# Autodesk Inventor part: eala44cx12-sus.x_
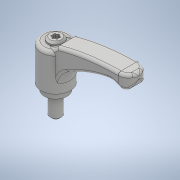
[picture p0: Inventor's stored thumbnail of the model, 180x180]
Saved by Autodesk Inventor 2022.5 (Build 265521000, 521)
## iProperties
Created: 2018-05
Part Number: eala44cx12-sus.x_
Material: 一般
Document SubType Name: Modeling
Designer: imaocorp
Density: 1 g/cm^3
Appearance: 既定
Sending System: SOLIDWORKS 2016-2016286
MC: AMD64
MC_MODEL: AMD64 Family 21 Model 2 Stepping 0, AuthenticAMD
OS: Windows_NT
FRU: Parasolid Version 28.0, build 224,  7-29-2016
FORMAT: text
GUISE: transmit
KEY: eala44cx12-sus
FILE: eala44cx12-sus.x_t
DATE: Fri May 18 11:28:47 2018
Author: imaocorp
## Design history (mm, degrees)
feature "Base1"
node "ソリッド1"
